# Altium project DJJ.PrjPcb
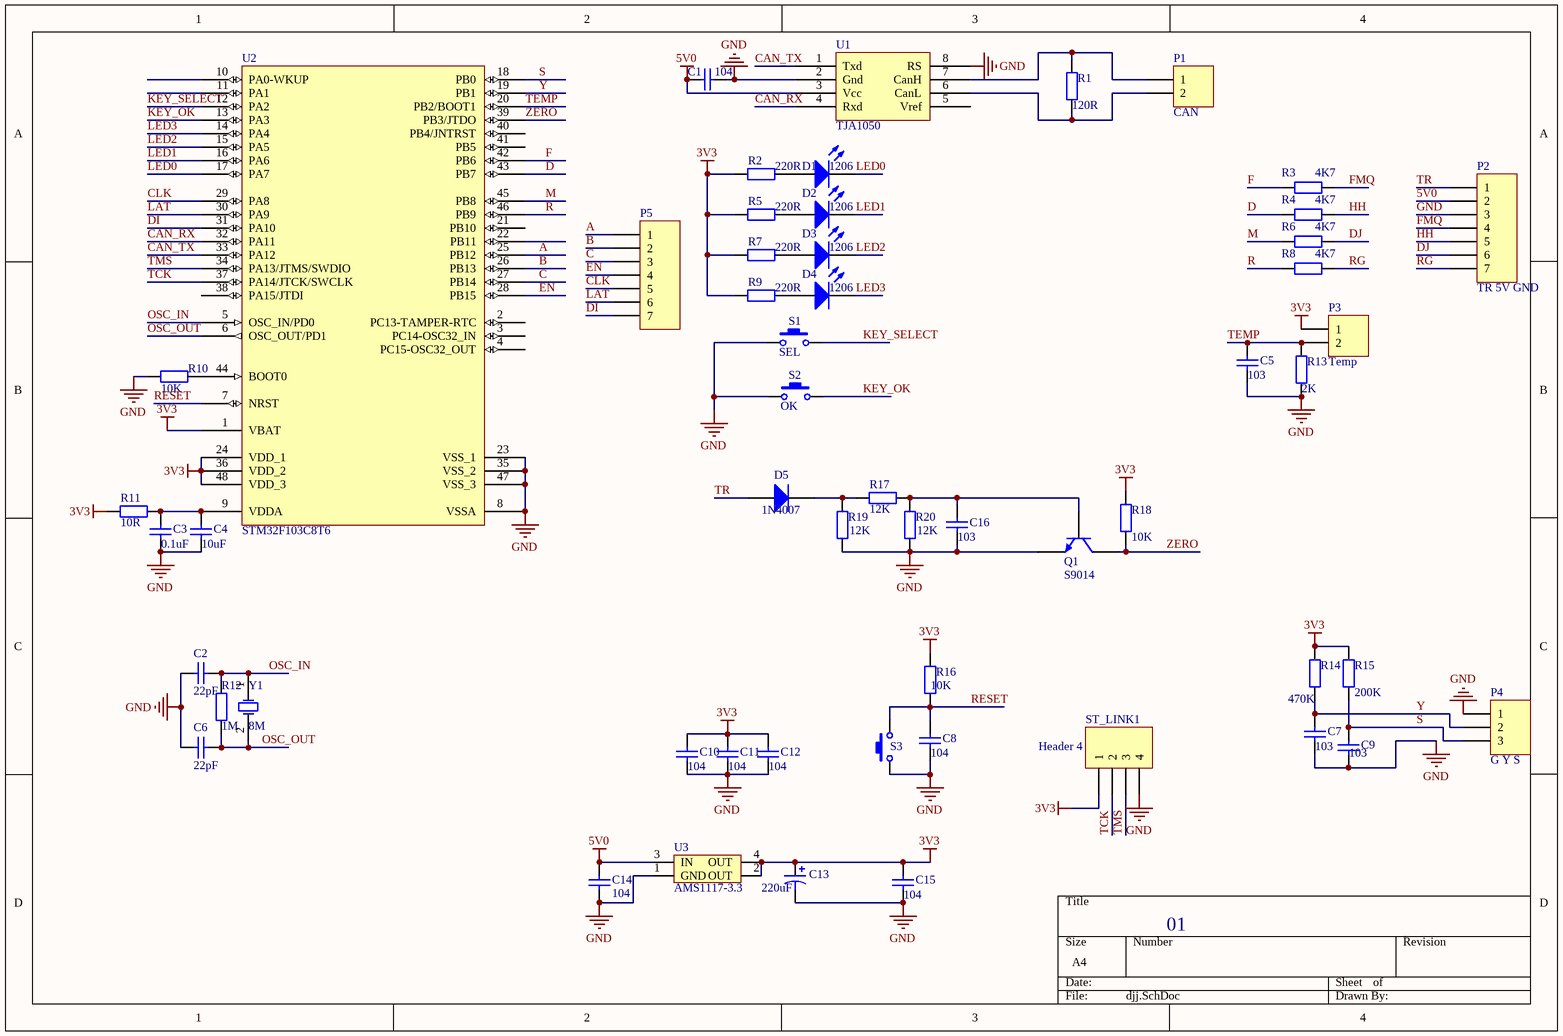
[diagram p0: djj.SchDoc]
1 sheet, 55 parts. Net scope: global (net labels, ports and power ports of the same name join across sheets).
Board file: PCB1.PcbDoc

## Sheet djj.SchDoc
size A4

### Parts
C1  value 104  [0603P]  (hidden comment: Cap)
C2  value 22pF  [0603P]  (hidden comment: Cap)
C3  value 0.1uF  [0603P]  (hidden comment: Cap)
C4  value 10uF  [0805_C]  (hidden comment: Cap)
C5  value 103  [0603P]  (hidden comment: Cap)
C6  value 22pF  [0603P]  (hidden comment: Cap)
C7  value 103  [0603P]  (hidden comment: Cap)
C8  value 104  [0603P]  (hidden comment: Cap)
C9  value 103  [0603P]  (hidden comment: Cap)
C10  value 104  [0603P]  (hidden comment: Cap)
C11  value 104  [0603P]  (hidden comment: Cap)
C12  value 104  [0603P]  (hidden comment: Cap)
C13  value 220uF  [CC6.56.5]  (hidden comment: Cap Pol1)
C14  value 104  [0603P]  (hidden comment: Cap)
C15  value 104  [0603P]  (hidden comment: Cap)
C16  value 103  [0805_C]  (hidden comment: Cap)
D1  1206  [1206]
D2  1206  [1206]
D3  1206  [1206]
D4  1206  [1206]
D5  1N4007  [DO-214AB]
P1  CAN  [2.54_2P]
P2  TR 5V GND  [2.54_7P]
P3  Temp  [2.54_2P]
P4  G Y S  [2.54_3P]
P5  (no value)  [2.54_7P]
Q1  S9014  [SOT23-3]
R1  value 120R  [0603P]  (hidden comment: Res2)
R2  value 220R  [0603P]  (hidden comment: Res2)
R3  value 4K7  [0603P]  (hidden comment: Res2)
R4  value 4K7  [0603P]  (hidden comment: Res2)
R5  value 220R  [0603P]  (hidden comment: Res2)
R6  value 4K7  [0603P]  (hidden comment: Res2)
R7  value 220R  [0603P]  (hidden comment: Res2)
R8  value 4K7  [0603P]  (hidden comment: Res2)
R9  value 220R  [0603P]  (hidden comment: Res2)
R10  value 10K  [0603P]  (hidden comment: Res2)
R11  value 10R  [0603P]  (hidden comment: Res2)
R12  value 1M  [0603P]  (hidden comment: Res2)
R13  value 2K  [0603P]  (hidden comment: Res2)
R14  value 470K  [0603P]  (hidden comment: Res2)
R15  value 200K  [0603P]  (hidden comment: Res2)
R16  value 10K  [0603P]  (hidden comment: Res2)
R17  value 12K  [0805_R]  (hidden comment: Res2)
R18  value 10K  [0603P]  (hidden comment: Res2)
R19  value 12K  [0805_R]  (hidden comment: Res2)
R20  value 12K  [0805_R]  (hidden comment: Res2)
S1  SEL  [KEY 6*6]
S2  OK  [KEY 6*6]
S3  RST  [KEY 6*6]  (value not drawn)
ST_LINK1  Header 4  [2.54_4P]
U1  TJA1050  [SO-8]
U2  STM32F103C8T6  [LQFP48S]
U3  AMS1117-3.3  [AMS1117]
Y1  8M  [XTAL_US]

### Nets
3V3: C10.2 C11.2 C12.2 C13.1 C15.2 P3.1 R2.1 R5.1 R7.1 R9.1 R11.1 R14.2 R15.2 R16.2 R18.2 ST_LINK1.1 U2.1(VBAT) U2.24(VDD_1) U2.36(VDD_2) U2.48(VDD_3) U3.2(OUT) U3.4(OUT)
5V0: C1.1 C14.1 P2.2 U1.3(Vcc) U3.3(IN)
GND: C1.2 C2.1 C3.1 C4.1 C5.1 C6.1 C7.1 C8.2 C9.1 C10.1 C11.1 C12.1 C13.2 C14.2 C15.1 C16.1 P2.3 P4.1 Q1.1(E) R10.1 R13.1 R19.1 R20.1 S1.1 S2.1 S3.1 ST_LINK1.4 U1.2(Gnd) U1.8(RS) U2.8(VSSA) U2.23(VSS_1) U2.35(VSS_2) U2.47(VSS_3) U3.1(GND)
A: P5.1 U2.25(PB12)
B: P5.2 U2.26(PB13)
C: P5.3 U2.27(PB14)
CAN_RX: U1.4(Rxd) U2.32(PA11)
CAN_TX: U1.1(Txd) U2.33(PA12)
CLK: P5.5 U2.29(PA8)
D: R4.2 U2.43(PB7)
DI: P5.7 U2.31(PA10)
DJ: P2.6 R6.1
EN: P5.4 U2.28(PB15)
F: R3.2 U2.42(PB6)
FMQ: P2.4 R3.1
HH: P2.5 R4.1
KEY_OK: S2.2 U2.13(PA3)
KEY_SELECT: S1.2 U2.12(PA2)
LAT: P5.6 U2.30(PA9)
LED0: D1.2(K) U2.17(PA7)
LED1: D2.2(K) U2.16(PA6)
LED2: D3.2(K) U2.15(PA5)
LED3: D4.2(K) U2.14(PA4)
M: R6.2 U2.45(PB8)
OSC_IN: C2.2 R12.1 U2.5(OSC_IN/PD0) Y1.1(OSC1)
OSC_OUT: C6.2 R12.2 U2.6(OSC_OUT/PD1) Y1.2(OSC2)
R: R8.2 U2.46(PB9)
RESET: C8.1 R16.1 S3.2 U2.7(NRST)
RG: P2.7 R8.1
S: C9.2 P4.3 R15.1 U2.18(PB0)
TCK: ST_LINK1.2 U2.37(PA14/JTCK/SWCLK)
TEMP: C5.2 P3.2 R13.2 U2.20(PB2/BOOT1)
TMS: ST_LINK1.3 U2.34(PA13/JTMS/SWDIO)
TR: D5.1(A) P2.1
Y: C7.2 P4.2 R14.1 U2.19(PB1)
ZERO: Q1.3(C) R18.1 U2.39(PB3/JTDO)
NetC3_2: C3.2 C4.2 R11.2 U2.9(VDDA)
NetC16_2: C16.2 Q1.2(B) R17.1 R20.2
NetD1_1: D1.1(A) R2.2
NetD2_1: D2.1(A) R5.2
NetD3_1: D3.1(A) R7.2
NetD4_1: D4.1(A) R9.2
NetD5_2: D5.2(K) R17.2 R19.2
NetP1_1: P1.1 R1.2 U1.7(CanH)
NetP1_2: P1.2 R1.1 U1.6(CanL)
NetR10_2: R10.2 U2.44(BOOT0)

Not connected (* = marked no-connect by the designer): U1 5(Vref); U2 2(PC13-TAMPER-RTC) 3(PC14-OSC32_IN) 4(PC15-OSC32_OUT) 10(PA0-WKUP) 11(PA1) 21(PB10) 22(PB11) 38(PA15/JTDI) 40(PB4/JNTRST) 41(PB5)

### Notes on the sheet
- 01

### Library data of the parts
C1-C12 C14-C16 = Cap: Capacitor
C13 = Cap Pol1: Polarized Capacitor (Radial)
D1-D4 = LED0: Typical INFRARED GaAs LED
D5 = Diode 1N4007: 1 Amp General Purpose Rectifier
P1 P3 = Header 2: Header, 2-Pin
P2 P5 = Header 7: Header, 7-Pin
P4 = Header 3: Header, 3-Pin
Q1 = 2N3904: NPN General Purpose Amplifier
R1-R20 = Res2: Resistor
S1-S3 = SW-PB: Switch
ST_LINK1 = Header 4: Header, 4-Pin
U3 = AMS1117
Y1 = XTAL: Crystal Oscillator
